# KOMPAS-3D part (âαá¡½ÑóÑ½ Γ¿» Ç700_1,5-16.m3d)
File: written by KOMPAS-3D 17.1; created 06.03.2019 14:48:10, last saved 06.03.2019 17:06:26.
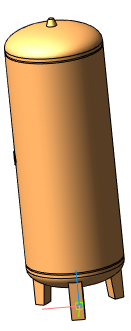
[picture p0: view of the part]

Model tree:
1. Операция без истории:3  (with: Сечение модели:1)

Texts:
  Гранлевел тип А100_1,5-16
  Гранлевел тип А150_1,5-16
  Гранлевел тип А220_1,5-16
  Гранлевел тип А350_1,5-16
  Гранлевел тип А500_1,5-16
  Гранлевел тип А700_1,5-16
  Гранлевел тип А900_1,5-16
  Гранлевел тип А1000_1,5-16
  Гранлевел тип А1400_1,5-16
  Точка начала. Х
  Точка начала. Y
  Точка начала. Z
